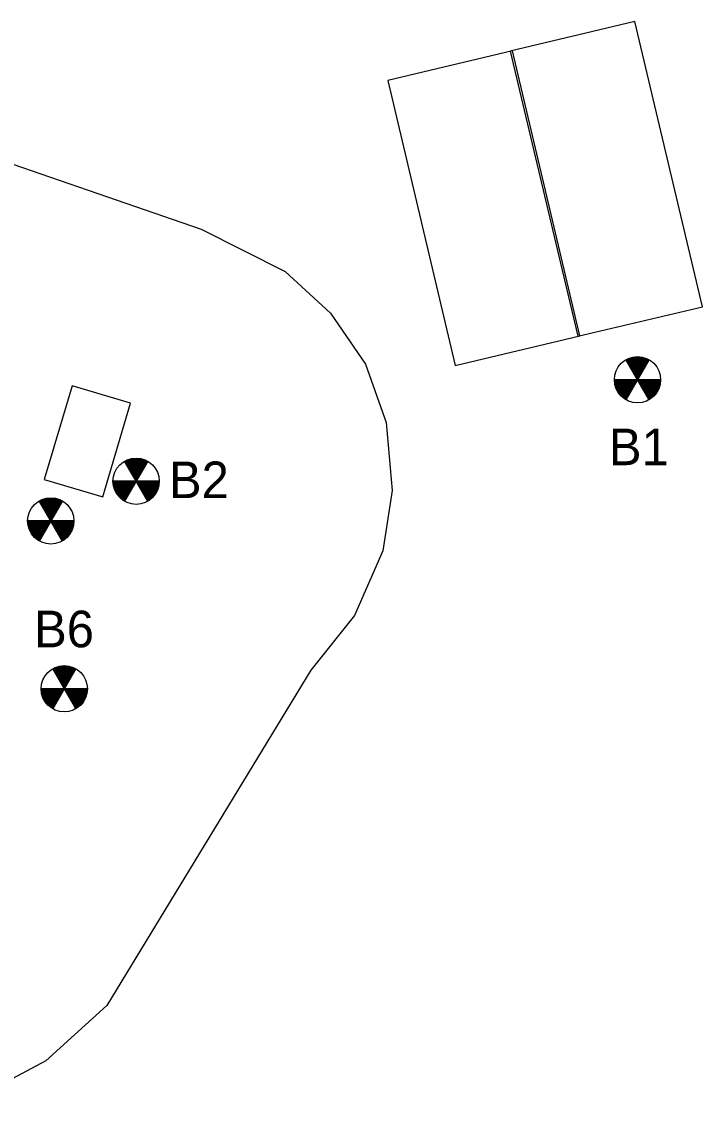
# Model space of a CAD drawing. Extents: x 1640347 to 1640460, y 843798 to 843906.
# Drawn here: x 1640404 to 1640459.9, y 843799.3 to 843887.5 of the extents above; entities that cross this region are included whole.
import ezdxf

# ---------------------------------------------------------------- set-up
doc = ezdxf.new("R2010")
doc.units = 0
for name, color, linetype in [('Boring Cell', 7, 'Continuous'), ('Exist Contamination Known - Area-Soil', 7, 'Continuous'), ('Exist Underground Storage Tank - Outline', 7, 'Continuous')]:
    doc.layers.add(name, color=color, linetype=linetype)

msp = doc.modelspace()

# ---------------------------------------------------------------- linework, layer by layer
at = {"layer": 'Boring Cell'}
for p, q in [((1640455.477, 843856.57), (1640453.58, 843859.856)), ((1640455.477, 843859.856), (1640453.58, 843856.57)), ((1640456.426, 843858.213), (1640452.632, 843858.213)), ((1640414.378, 843848.252), (1640412.481, 843851.539)), ((1640414.378, 843851.539), (1640412.481, 843848.252)), ((1640415.326, 843849.896), (1640411.532, 843849.896)), ((1640407.383, 843844.999), (1640405.486, 843848.285)), ((1640407.383, 843848.285), (1640405.486, 843844.999)), ((1640408.332, 843846.642), (1640404.537, 843846.642)), ((1640408.492, 843831.259), (1640406.595, 843834.545)), ((1640408.492, 843834.545), (1640406.595, 843831.259)), ((1640409.441, 843832.902), (1640405.646, 843832.902))]:
    msp.add_line(p, q, dxfattribs=at)
for centre in [(1640454.529, 843858.213), (1640413.429, 843849.896), (1640406.435, 843846.642), (1640407.543, 843832.902)]:
    msp.add_circle(centre, 1.897, dxfattribs=at)
for centre, radius, start, end in [((1640454.529, 843858.213), 1.837, 60, 120), ((1640454.529, 843858.213), 1.777, 60, 120), ((1640454.529, 843858.213), 1.717, 60, 120), ((1640454.529, 843858.213), 1.657, 60, 120), ((1640454.529, 843858.213), 1.597, 60, 120), ((1640454.529, 843858.213), 1.537, 60, 120), ((1640454.529, 843858.213), 1.477, 60, 120), ((1640454.529, 843858.213), 1.417, 60, 120), ((1640454.529, 843858.213), 1.357, 60, 120), ((1640454.529, 843858.213), 1.297, 60, 120), ((1640454.529, 843858.213), 1.237, 60, 120), ((1640454.529, 843858.213), 1.177, 60, 120), ((1640454.529, 843858.213), 1.117, 60, 120), ((1640454.529, 843858.213), 1.057, 60, 120), ((1640454.529, 843858.213), 0.997, 60, 120), ((1640454.529, 843858.213), 0.937, 60, 120), ((1640454.529, 843858.213), 0.877, 60, 120), ((1640454.529, 843858.213), 0.817, 60, 120), ((1640454.529, 843858.213), 0.757, 60, 120), ((1640454.529, 843858.213), 0.697, 60, 120), ((1640454.529, 843858.213), 0.637, 60, 120), ((1640454.529, 843858.213), 0.577, 60, 120), ((1640454.529, 843858.213), 0.517, 60, 120), ((1640454.529, 843858.213), 0.457, 60, 120), ((1640454.529, 843858.213), 0.397, 60, 120), ((1640454.529, 843858.213), 1.837, 180, 240), ((1640454.529, 843858.213), 1.777, 180, 240), ((1640454.529, 843858.213), 1.717, 180, 240), ((1640454.529, 843858.213), 1.657, 180, 240), ((1640454.529, 843858.213), 1.597, 180, 240), ((1640454.529, 843858.213), 1.537, 180, 240), ((1640454.529, 843858.213), 1.477, 180, 240), ((1640454.529, 843858.213), 1.417, 180, 240), ((1640454.529, 843858.213), 1.357, 180, 240), ((1640454.529, 843858.213), 1.297, 180, 240), ((1640454.529, 843858.213), 1.237, 180, 240), ((1640454.529, 843858.213), 1.177, 180, 240), ((1640454.529, 843858.213), 1.117, 180, 240), ((1640454.529, 843858.213), 1.057, 180, 240), ((1640454.529, 843858.213), 0.997, 180, 240), ((1640454.529, 843858.213), 0.937, 180, 240), ((1640454.529, 843858.213), 0.877, 180, 240), ((1640454.529, 843858.213), 0.817, 180, 240), ((1640454.529, 843858.213), 0.757, 180, 240), ((1640454.529, 843858.213), 0.697, 180, 240), ((1640454.529, 843858.213), 0.637, 180, 240), ((1640454.529, 843858.213), 0.577, 180, 240), ((1640454.529, 843858.213), 0.517, 180, 240), ((1640454.529, 843858.213), 0.457, 180, 240), ((1640454.529, 843858.213), 0.397, 180, 240), ((1640454.529, 843858.213), 0.337, 180, 240), ((1640454.529, 843858.213), 0.277, 180, 240), ((1640454.529, 843858.213), 0.217, 180, 240), ((1640454.529, 843858.213), 0.337, 60, 120), ((1640454.529, 843858.213), 0.157, 180, 240), ((1640454.529, 843858.213), 0.277, 60, 120), ((1640454.529, 843858.213), 0.217, 60, 120), ((1640454.529, 843858.213), 0.0972, 180, 240), ((1640454.529, 843858.213), 0.157, 60, 120), ((1640454.529, 843858.213), 0.0972, 60, 120), ((1640454.529, 843858.213), 0.0972, 300, 0), ((1640454.529, 843858.213), 0.157, 300, 0), ((1640454.529, 843858.213), 0.217, 300, 0), ((1640454.529, 843858.213), 0.277, 300, 0), ((1640454.529, 843858.213), 0.337, 300, 360), ((1640454.529, 843858.213), 0.397, 300, 0), ((1640454.529, 843858.213), 0.457, 300, 360), ((1640454.529, 843858.213), 0.517, 300, 0), ((1640454.529, 843858.213), 0.577, 300, 0), ((1640454.529, 843858.213), 0.637, 300, 0), ((1640454.529, 843858.213), 0.697, 300, 0), ((1640454.529, 843858.213), 0.757, 300, 0), ((1640454.529, 843858.213), 0.817, 300, 0), ((1640454.529, 843858.213), 0.877, 300, 0), ((1640454.529, 843858.213), 0.937, 300, 0), ((1640454.529, 843858.213), 0.997, 300, 0), ((1640454.529, 843858.213), 1.057, 300, 0), ((1640454.529, 843858.213), 1.117, 300, 0), ((1640454.529, 843858.213), 1.177, 300, 0), ((1640454.529, 843858.213), 1.237, 300, 360), ((1640454.529, 843858.213), 1.297, 300, 0), ((1640454.529, 843858.213), 1.357, 300, 0), ((1640454.529, 843858.213), 1.417, 300, 0), ((1640454.529, 843858.213), 1.477, 300, 0), ((1640454.529, 843858.213), 1.537, 300, 0), ((1640454.529, 843858.213), 1.597, 300, 0), ((1640454.529, 843858.213), 1.657, 300, 360), ((1640454.529, 843858.213), 1.717, 300, 0), ((1640454.529, 843858.213), 1.777, 300, 0), ((1640454.529, 843858.213), 1.837, 300, 0), ((1640413.429, 843849.896), 1.837, 60, 120), ((1640413.429, 843849.896), 1.777, 60, 120), ((1640413.429, 843849.896), 1.717, 60, 120), ((1640413.429, 843849.896), 1.657, 60, 120), ((1640413.429, 843849.896), 1.597, 60, 120), ((1640413.429, 843849.896), 1.537, 60, 120), ((1640413.429, 843849.896), 1.477, 60, 120), ((1640413.429, 843849.896), 1.417, 60, 120), ((1640413.429, 843849.896), 1.357, 60, 120), ((1640413.429, 843849.896), 1.297, 60, 120), ((1640413.429, 843849.896), 1.237, 60, 120), ((1640413.429, 843849.896), 1.177, 60, 120), ((1640413.429, 843849.896), 1.117, 60, 120), ((1640413.429, 843849.896), 1.057, 60, 120), ((1640413.429, 843849.896), 0.997, 60, 120), ((1640413.429, 843849.896), 0.937, 60, 120), ((1640413.429, 843849.896), 0.877, 60, 120), ((1640413.429, 843849.896), 0.817, 60, 120), ((1640413.429, 843849.896), 0.757, 60, 120), ((1640413.429, 843849.896), 1.837, 180, 240), ((1640413.429, 843849.896), 1.777, 180, 240), ((1640413.429, 843849.896), 1.717, 180, 240), ((1640413.429, 843849.896), 1.657, 180, 240), ((1640413.429, 843849.896), 1.597, 180, 240), ((1640413.429, 843849.896), 1.537, 180, 240), ((1640413.429, 843849.896), 1.477, 180, 240), ((1640413.429, 843849.896), 1.417, 180, 240), ((1640413.429, 843849.896), 1.357, 180, 240), ((1640413.429, 843849.896), 1.297, 180, 240), ((1640413.429, 843849.896), 1.237, 180, 240), ((1640413.429, 843849.896), 1.177, 180, 240), ((1640413.429, 843849.896), 1.117, 180, 240), ((1640413.429, 843849.896), 1.057, 180, 240), ((1640413.429, 843849.896), 0.997, 180, 240), ((1640413.429, 843849.896), 0.937, 180, 240), ((1640413.429, 843849.896), 0.877, 180, 240), ((1640413.429, 843849.896), 0.817, 180, 240), ((1640413.429, 843849.896), 0.757, 180, 240), ((1640413.429, 843849.896), 0.697, 180, 240), ((1640413.429, 843849.896), 0.637, 180, 240), ((1640413.429, 843849.896), 0.577, 180, 240), ((1640413.429, 843849.896), 0.517, 180, 240), ((1640413.429, 843849.896), 0.457, 180, 240), ((1640413.429, 843849.896), 0.397, 180, 240), ((1640413.429, 843849.896), 0.697, 60, 120), ((1640413.429, 843849.896), 0.337, 180, 240), ((1640413.429, 843849.896), 0.637, 60, 120), ((1640413.429, 843849.896), 0.577, 60, 120), ((1640413.429, 843849.896), 0.277, 180, 240), ((1640413.429, 843849.896), 0.517, 60, 120), ((1640413.429, 843849.896), 0.457, 60, 120), ((1640413.429, 843849.896), 0.217, 180, 240), ((1640413.429, 843849.896), 0.397, 60, 120), ((1640413.429, 843849.896), 0.337, 60, 120), ((1640413.429, 843849.896), 0.157, 180, 240), ((1640413.429, 843849.896), 0.277, 60, 120), ((1640413.429, 843849.896), 0.217, 60, 120), ((1640413.429, 843849.896), 0.0972, 180, 240), ((1640413.429, 843849.896), 0.157, 60, 120), ((1640413.429, 843849.896), 0.0972, 60, 120), ((1640413.429, 843849.896), 0.0972, 300, 0), ((1640413.429, 843849.896), 0.157, 300, 0), ((1640413.429, 843849.896), 0.217, 300, 0), ((1640413.429, 843849.896), 0.277, 300, 0), ((1640413.429, 843849.896), 0.337, 300, 360), ((1640413.429, 843849.896), 0.397, 300, 0), ((1640413.429, 843849.896), 0.457, 300, 360), ((1640413.429, 843849.896), 0.517, 300, 0), ((1640413.429, 843849.896), 0.577, 300, 0), ((1640413.429, 843849.896), 0.637, 300, 0), ((1640413.429, 843849.896), 0.697, 300, 0), ((1640413.429, 843849.896), 0.757, 300, 0), ((1640413.429, 843849.896), 0.817, 300, 0), ((1640413.429, 843849.896), 0.877, 300, 0), ((1640413.429, 843849.896), 0.937, 300, 0), ((1640413.429, 843849.896), 0.997, 300, 0), ((1640413.429, 843849.896), 1.057, 300, 0), ((1640413.429, 843849.896), 1.117, 300, 0), ((1640413.429, 843849.896), 1.177, 300, 0), ((1640413.429, 843849.896), 1.237, 300, 360), ((1640413.429, 843849.896), 1.297, 300, 0), ((1640413.429, 843849.896), 1.357, 300, 0), ((1640413.429, 843849.896), 1.417, 300, 0), ((1640413.429, 843849.896), 1.477, 300, 0), ((1640413.429, 843849.896), 1.537, 300, 0), ((1640413.429, 843849.896), 1.597, 300, 0), ((1640413.429, 843849.896), 1.657, 300, 360), ((1640413.429, 843849.896), 1.717, 300, 0), ((1640413.429, 843849.896), 1.777, 300, 0), ((1640413.429, 843849.896), 1.837, 300, 0), ((1640406.435, 843846.642), 1.837, 60, 120), ((1640406.435, 843846.642), 1.777, 60, 120), ((1640406.435, 843846.642), 1.717, 60, 120), ((1640406.435, 843846.642), 1.657, 60, 120), ((1640406.435, 843846.642), 1.597, 60, 120), ((1640406.435, 843846.642), 1.537, 60, 120), ((1640406.435, 843846.642), 1.477, 60, 120), ((1640406.435, 843846.642), 1.417, 60, 120), ((1640406.435, 843846.642), 1.357, 60, 120), ((1640406.435, 843846.642), 1.297, 60, 120), ((1640406.435, 843846.642), 1.237, 60, 120), ((1640406.435, 843846.642), 1.177, 60, 120), ((1640406.435, 843846.642), 1.117, 60, 120), ((1640406.435, 843846.642), 1.057, 60, 120), ((1640406.435, 843846.642), 0.997, 60, 120), ((1640406.435, 843846.642), 0.937, 60, 120), ((1640406.435, 843846.642), 0.877, 60, 120), ((1640406.435, 843846.642), 0.817, 60, 120), ((1640406.435, 843846.642), 0.757, 60, 120), ((1640406.435, 843846.642), 0.697, 60, 120), ((1640406.435, 843846.642), 0.637, 60, 120), ((1640406.435, 843846.642), 0.577, 60, 120), ((1640406.435, 843846.642), 0.517, 60, 120), ((1640406.435, 843846.642), 1.837, 180, 240), ((1640406.435, 843846.642), 1.777, 180, 240), ((1640406.435, 843846.642), 1.717, 180, 240), ((1640406.435, 843846.642), 1.657, 180, 240), ((1640406.435, 843846.642), 1.597, 180, 240), ((1640406.435, 843846.642), 1.537, 180, 240), ((1640406.435, 843846.642), 1.477, 180, 240), ((1640406.435, 843846.642), 1.417, 180, 240), ((1640406.435, 843846.642), 1.357, 180, 240), ((1640406.435, 843846.642), 1.297, 180, 240), ((1640406.435, 843846.642), 1.237, 180, 240), ((1640406.435, 843846.642), 1.177, 180, 240), ((1640406.435, 843846.642), 1.117, 180, 240), ((1640406.435, 843846.642), 1.057, 180, 240), ((1640406.435, 843846.642), 0.997, 180, 240), ((1640406.435, 843846.642), 0.937, 180, 240), ((1640406.435, 843846.642), 0.877, 180, 240), ((1640406.435, 843846.642), 0.817, 180, 240), ((1640406.435, 843846.642), 0.757, 180, 240), ((1640406.435, 843846.642), 0.697, 180, 240), ((1640406.435, 843846.642), 0.637, 180, 240), ((1640406.435, 843846.642), 0.577, 180, 240), ((1640406.435, 843846.642), 0.517, 180, 240), ((1640406.435, 843846.642), 0.457, 180, 240), ((1640406.435, 843846.642), 0.397, 180, 240), ((1640406.435, 843846.642), 0.337, 180, 240), ((1640406.435, 843846.642), 0.277, 180, 240), ((1640406.435, 843846.642), 0.457, 60, 120), ((1640406.435, 843846.642), 0.217, 180, 240), ((1640406.435, 843846.642), 0.397, 60, 120), ((1640406.435, 843846.642), 0.337, 60, 120), ((1640406.435, 843846.642), 0.157, 180, 240), ((1640406.435, 843846.642), 0.277, 60, 120), ((1640406.435, 843846.642), 0.217, 60, 120), ((1640406.435, 843846.642), 0.0972, 180, 240), ((1640406.435, 843846.642), 0.157, 60, 120), ((1640406.435, 843846.642), 0.0972, 60, 120), ((1640406.435, 843846.642), 0.0972, 300, 0), ((1640406.435, 843846.642), 0.157, 300, 0), ((1640406.435, 843846.642), 0.217, 300, 0), ((1640406.435, 843846.642), 0.277, 300, 0), ((1640406.435, 843846.642), 0.337, 300, 360), ((1640406.435, 843846.642), 0.397, 300, 0), ((1640406.435, 843846.642), 0.457, 300, 360), ((1640406.435, 843846.642), 0.517, 300, 0), ((1640406.435, 843846.642), 0.577, 300, 0), ((1640406.435, 843846.642), 0.637, 300, 0), ((1640406.435, 843846.642), 0.697, 300, 0), ((1640406.435, 843846.642), 0.757, 300, 0), ((1640406.435, 843846.642), 0.817, 300, 0), ((1640406.435, 843846.642), 0.877, 300, 0), ((1640406.435, 843846.642), 0.937, 300, 0), ((1640406.435, 843846.642), 0.997, 300, 0), ((1640406.435, 843846.642), 1.057, 300, 0), ((1640406.435, 843846.642), 1.117, 300, 0), ((1640406.435, 843846.642), 1.177, 300, 0), ((1640406.435, 843846.642), 1.237, 300, 360), ((1640406.435, 843846.642), 1.297, 300, 0), ((1640406.435, 843846.642), 1.357, 300, 0), ((1640406.435, 843846.642), 1.417, 300, 0), ((1640406.435, 843846.642), 1.477, 300, 0), ((1640406.435, 843846.642), 1.537, 300, 0), ((1640406.435, 843846.642), 1.597, 300, 0), ((1640406.435, 843846.642), 1.657, 300, 360), ((1640406.435, 843846.642), 1.717, 300, 0), ((1640406.435, 843846.642), 1.777, 300, 0), ((1640406.435, 843846.642), 1.837, 300, 0), ((1640407.543, 843832.902), 1.837, 60, 120), ((1640407.543, 843832.902), 1.777, 60, 120), ((1640407.543, 843832.902), 1.717, 60, 120), ((1640407.543, 843832.902), 1.657, 60, 120), ((1640407.543, 843832.902), 1.597, 60, 120), ((1640407.543, 843832.902), 1.537, 60, 120), ((1640407.543, 843832.902), 1.477, 60, 120), ((1640407.543, 843832.902), 1.417, 60, 120), ((1640407.543, 843832.902), 1.357, 60, 120), ((1640407.543, 843832.902), 1.297, 60, 120), ((1640407.543, 843832.902), 1.237, 60, 120), ((1640407.543, 843832.902), 1.177, 60, 120), ((1640407.543, 843832.902), 1.117, 60, 120), ((1640407.543, 843832.902), 1.057, 60, 120), ((1640407.543, 843832.902), 0.997, 60, 120), ((1640407.543, 843832.902), 0.937, 60, 120), ((1640407.543, 843832.902), 0.877, 60, 120), ((1640407.543, 843832.902), 0.817, 60, 120), ((1640407.543, 843832.902), 0.757, 60, 120), ((1640407.543, 843832.902), 0.697, 60, 120), ((1640407.543, 843832.902), 0.637, 60, 120), ((1640407.543, 843832.902), 0.577, 60, 120), ((1640407.543, 843832.902), 0.517, 60, 120), ((1640407.543, 843832.902), 0.457, 60, 120), ((1640407.543, 843832.902), 0.397, 60, 120), ((1640407.543, 843832.902), 0.337, 60, 120), ((1640407.543, 843832.902), 0.277, 60, 120), ((1640407.543, 843832.902), 0.217, 60, 120), ((1640407.543, 843832.902), 0.157, 60, 120), ((1640407.543, 843832.902), 0.0972, 60, 120), ((1640407.543, 843832.902), 1.837, 180, 240), ((1640407.543, 843832.902), 1.777, 180, 240), ((1640407.543, 843832.902), 1.717, 180, 240), ((1640407.543, 843832.902), 1.657, 180, 240), ((1640407.543, 843832.902), 1.597, 180, 240), ((1640407.543, 843832.902), 1.537, 180, 240), ((1640407.543, 843832.902), 1.477, 180, 240), ((1640407.543, 843832.902), 1.417, 180, 240), ((1640407.543, 843832.902), 1.357, 180, 240), ((1640407.543, 843832.902), 1.297, 180, 240), ((1640407.543, 843832.902), 1.237, 180, 240), ((1640407.543, 843832.902), 1.177, 180, 240), ((1640407.543, 843832.902), 1.117, 180, 240), ((1640407.543, 843832.902), 1.057, 180, 240), ((1640407.543, 843832.902), 0.997, 180, 240), ((1640407.543, 843832.902), 0.937, 180, 240), ((1640407.543, 843832.902), 0.877, 180, 240), ((1640407.543, 843832.902), 0.817, 180, 240), ((1640407.543, 843832.902), 0.757, 180, 240), ((1640407.543, 843832.902), 0.697, 180, 240), ((1640407.543, 843832.902), 0.637, 180, 240), ((1640407.543, 843832.902), 0.577, 180, 240), ((1640407.543, 843832.902), 0.517, 180, 240), ((1640407.543, 843832.902), 0.457, 180, 240), ((1640407.543, 843832.902), 0.397, 180, 240), ((1640407.543, 843832.902), 0.337, 180, 240), ((1640407.543, 843832.902), 0.277, 180, 240), ((1640407.543, 843832.902), 0.217, 180, 240), ((1640407.543, 843832.902), 0.157, 180, 240), ((1640407.543, 843832.902), 0.0972, 180, 240), ((1640407.543, 843832.902), 0.0972, 300, 0), ((1640407.543, 843832.902), 0.157, 300, 0), ((1640407.543, 843832.902), 0.217, 300, 0), ((1640407.543, 843832.902), 0.277, 300, 0), ((1640407.543, 843832.902), 0.337, 300, 360), ((1640407.543, 843832.902), 0.397, 300, 0), ((1640407.543, 843832.902), 0.457, 300, 360), ((1640407.543, 843832.902), 0.517, 300, 0), ((1640407.543, 843832.902), 0.577, 300, 0), ((1640407.543, 843832.902), 0.637, 300, 0), ((1640407.543, 843832.902), 0.697, 300, 0), ((1640407.543, 843832.902), 0.757, 300, 0), ((1640407.543, 843832.902), 0.817, 300, 0), ((1640407.543, 843832.902), 0.877, 300, 0), ((1640407.543, 843832.902), 0.937, 300, 0), ((1640407.543, 843832.902), 0.997, 300, 0), ((1640407.543, 843832.902), 1.057, 300, 0), ((1640407.543, 843832.902), 1.117, 300, 0), ((1640407.543, 843832.902), 1.177, 300, 0), ((1640407.543, 843832.902), 1.237, 300, 360), ((1640407.543, 843832.902), 1.297, 300, 0), ((1640407.543, 843832.902), 1.357, 300, 0), ((1640407.543, 843832.902), 1.417, 300, 0), ((1640407.543, 843832.902), 1.477, 300, 0), ((1640407.543, 843832.902), 1.537, 300, 0), ((1640407.543, 843832.902), 1.597, 300, 0), ((1640407.543, 843832.902), 1.657, 300, 360), ((1640407.543, 843832.902), 1.717, 300, 0), ((1640407.543, 843832.902), 1.777, 300, 0), ((1640407.543, 843832.902), 1.837, 300, 0)]:
    msp.add_arc(centre, radius, start, end, dxfattribs=at)
at = {"layer": 'Exist Contamination Known - Area-Soil'}
msp.add_lwpolyline([(1640397.83, 843877.738), (1640418.761, 843870.539), (1640425.635, 843867.086), (1640429.373, 843863.667), (1640432.224, 843859.48), (1640433.937, 843854.712), (1640434.428, 843849.134), (1640433.645, 843844.183), (1640431.331, 843838.912), (1640427.74, 843834.412), (1640411.023, 843806.962), (1640406.04, 843802.412), (1640400.072, 843799.262)], dxfattribs=at)
at = {"layer": 'Exist Underground Storage Tank - Outline'}
for points in [[(1640454.316, 843887.548), (1640444.099, 843885.126), (1640449.635, 843861.773), (1640459.852, 843864.195)], [(1640444.269, 843885.146), (1640434.052, 843882.723), (1640439.589, 843859.371), (1640449.805, 843861.793)], [(1640412.968, 843856.281), (1640408.174, 843857.702), (1640405.901, 843850.032), (1640410.695, 843848.611)]]:
    msp.add_lwpolyline(points, close=True, dxfattribs=at)

# ---------------------------------------------------------------- texts
at = {"layer": 'Boring Cell'}
for s, p in [('B1', (1640452.184, 843851.211)), ('B2', (1640416.12, 843848.511)), ('B6', (1640405.069, 843836.294))]:
    msp.add_text(s, height=3, dxfattribs=at).set_placement(p)

doc.saveas('drawing.dxf')
